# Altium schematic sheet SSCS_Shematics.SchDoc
size 304 x 199 mm; SheetNumber: 1; SheetTotal: 1
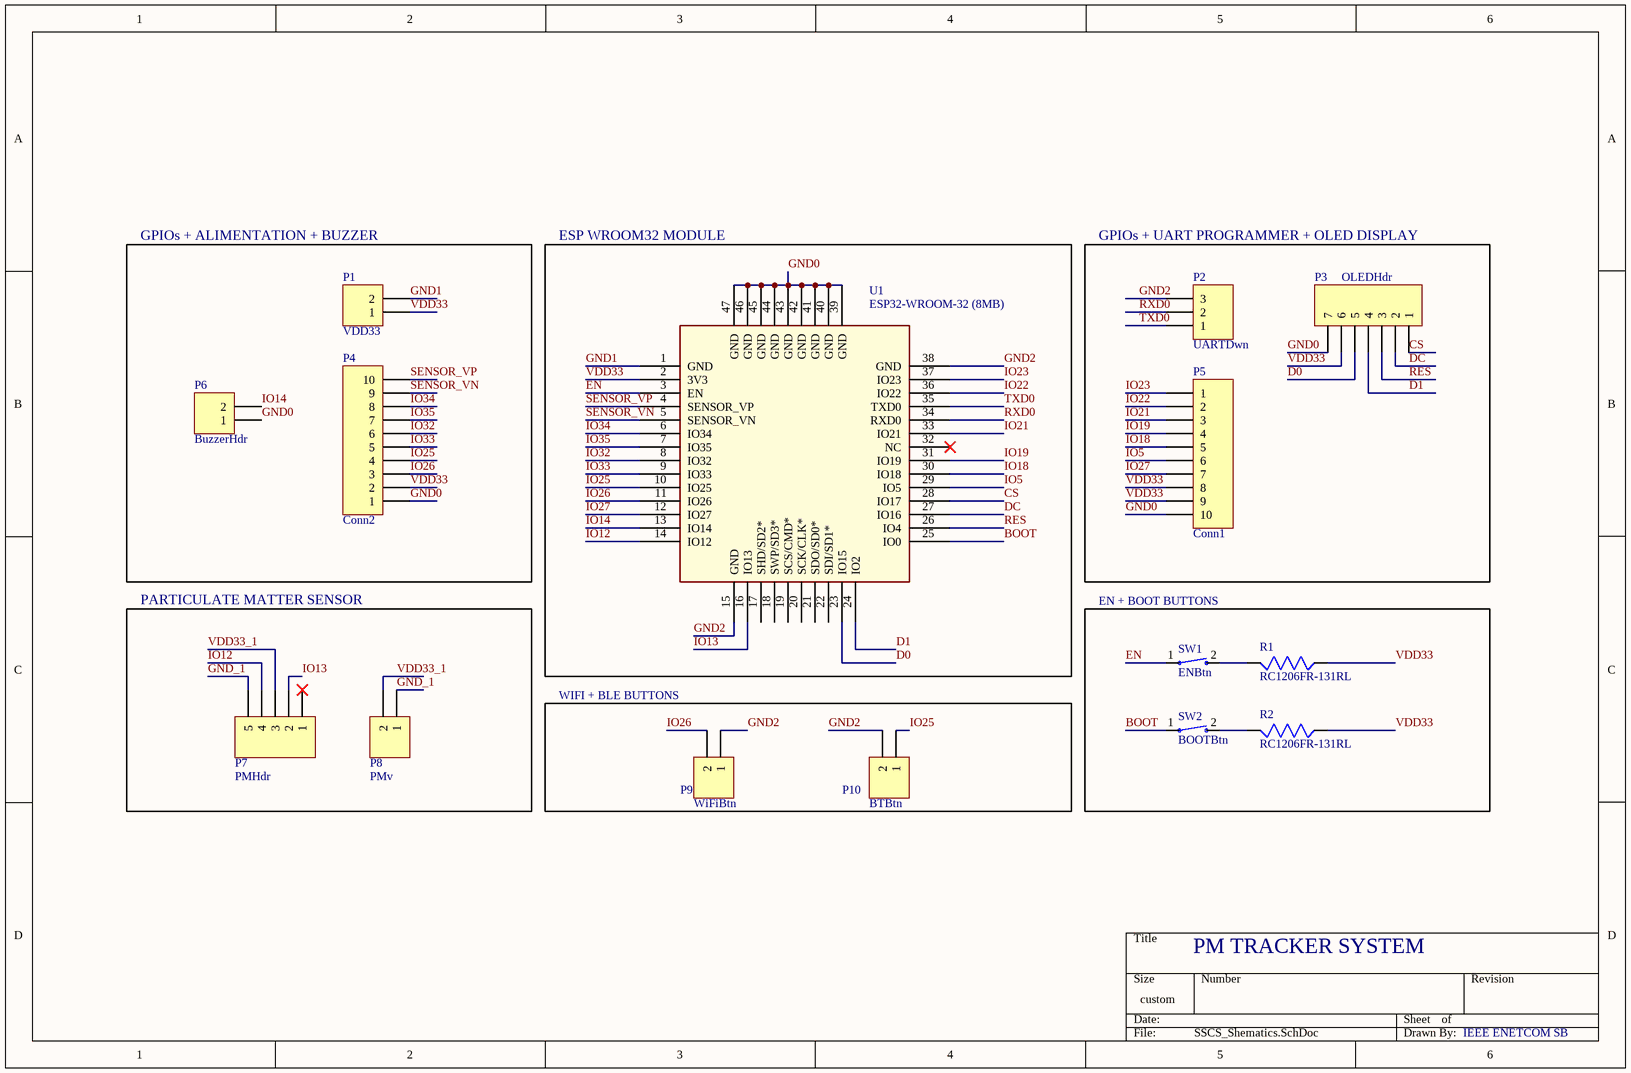
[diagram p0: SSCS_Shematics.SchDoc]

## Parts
P1  VDD33  [Conn2x2.54]
P2  UARTDwn  [Conn3x2.54]
P3  OLEDHdr  [Conn7x2.54]
P4  Conn2  [Conn10x2.54]
P5  Conn1  [Conn10x2.54]
P6  BuzzerHdr  [Conn2x2.54Buzzer]
P7  PMHdr  [Conn5x2.54]
P8  PMv  [Conn2x2.54]
P9  WiFiBtn  [SW]
P10  BTBtn  [SW]
R1  RC1206FR-131RL  [res]
R2  RC1206FR-131RL  [res]
SW1  ENBtn  [SW]
SW2  BOOTBtn  [SW]
U1  ESP32-WROOM-32 (8MB)  [IC38_ESP32-WROOM-32 8MB_EXP]

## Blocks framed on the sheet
GPIOs + ALIMENTATION + BUZZER: P1 P4 P6
ESP WROOM32 MODULE: U1
GPIOs + UART PROGRAMMER + OLED DISPLAY: P2 P3 P5
PARTICULATE MATTER SENSOR: P7 P8
EN + BOOT BUTTONS: R1 R2 SW1 SW2
WIFI + BLE BUTTONS: P9 P10

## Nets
BOOT: SW2.1 U1.25(IO0)
CS: P3.1 U1.28(IO17)
D0: P3.5 U1.23(IO15)
D1: P3.4 U1.24(IO2)
DC: P3.2 U1.27(IO16)
EN: SW1.1 U1.3(EN)
GND0: P3.7 P4.1 P5.10 P6.1 U1.39(GND) U1.40(GND) U1.41(GND) U1.42(GND) U1.43(GND) U1.44(GND) U1.45(GND) U1.46(GND) U1.47(GND)
GND1: P1.2 U1.1(GND)
GND2: P2.3 P9.1 P10.2 U1.15(GND) U1.38(GND)
GND_1: P7.5 P8.1
IO5: P5.6 U1.29(IO5)
IO12: P7.4 U1.14(IO12)
IO13: P7.2 U1.16(IO13)
IO14: P6.2 U1.13(IO14)
IO18: P5.5 U1.30(IO18)
IO19: P5.4 U1.31(IO19)
IO21: P5.3 U1.33(IO21)
IO22: P5.2 U1.36(IO22)
IO23: P5.1 U1.37(IO23)
IO25: P4.4 P10.1 U1.10(IO25)
IO26: P4.3 P9.2 U1.11(IO26)
IO27: P5.7 U1.12(IO27)
IO32: P4.6 U1.8(IO32)
IO33: P4.5 U1.9(IO33)
IO34: P4.8 U1.6(IO34)
IO35: P4.7 U1.7(IO35)
RES: P3.3 U1.26(IO4)
RXD0: P2.2 U1.34(RXD0)
SENSOR_VN: P4.9 U1.5(SENSOR_VN)
SENSOR_VP: P4.10 U1.4(SENSOR_VP)
TXD0: P2.1 U1.35(TXD0)
VDD33: P1.1 P3.6 P4.2 P5.8 P5.9 R1.2 R2.2 U1.2(3V3)
VDD33_1: P7.3 P8.2
NetR1_1: R1.1 SW1.2
NetR2_1: R2.1 SW2.2

Not connected (* = marked no-connect by the designer): P7 1*; U1 17(SHD/SD2*) 18(SWP/SD3*) 19(SCS/CMD*) 20(SCK/CLK*) 21(SDO/SD0*) 22(SDI/SD1*) 32(NC)*

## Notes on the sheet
- PM TRACKER SYSTEM
- IEEE ENETCOM SB

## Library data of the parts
P1 P6 P8-P10 = MHDR1X2: Header, 2-Pin
P2 = MHDR1X3: Header, 3-Pin
P3 = MHDR1X7: Header, 7-Pin
P4 P5 = MHDR1X10: Header, 10-Pin
P7 = MHDR1X5: Header, 5-Pin
R1 R2 = RC1206FR-131RL: RC Series 1206 0.25 W 0 O Jumper Surface Mount Thick Film Chip Resistor
SW1 SW2 = 147873-1: Switch Tactile OFF (ON) SPST Rectangular Button J-Bend 0.05A 24VDC 1.77N SMD T/R; MF: TE Connectivity
U1 = ESP32-WROOM-32 8MB: No Description Available; Mfr_Name: Espressif Systems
